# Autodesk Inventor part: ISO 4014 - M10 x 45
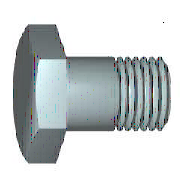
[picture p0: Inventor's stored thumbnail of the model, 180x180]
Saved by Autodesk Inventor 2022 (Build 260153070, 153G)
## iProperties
Created: 2021-02
Part Number: ISO 4014 - M10 x 45
Material: Acier inoxydable 440C
Description: Boulon à tête hexagonale - Produit de classes A et B
Document SubType Name: Modeling
Standard: ISO 4014
Designer: Fabian
Standard Revision: Fourth edition 2011-03-15
Standards Organization: ISO
Language: fr-FR
Size Designation: M10 x 45
Categories: <MemberInstance><Categories><Category DisplayName="Visserie" InternalName="e4da775c-781d-43d5-af7c-5136215cf5a6" Mnemonic="FSTN"><Category DisplayName="Vis" Int
Density: 7.75 g/cm^3
Appearance: Semi-poli
IsCustomPart: 0
Author: Fabian
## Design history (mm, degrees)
sketch "Esquisse1"
  geometry: L1 (0, 7.315)-(0, 5); L2 (19, 5)-(45, 5); L3 (45, 5)-(45, 0); L4 (45, 0)-(-0.6, 0); L5 (-9.72, 0)-(54.12, 0) reference; L6 (-0.6, 0)-(-0.6, 7.315); L7 (-0.6, 7.315)-(0, 7.315); L8 (19, 5)-(18.08, 5); L9 (18.08, 5)-(0, 5); L10 (0, -1.463)-(0, 8.778) reference
  constraints: 16 end point, 2 collinear, 2 perpendicular, 1 parallel
  dimensions: "d0" = 45 distance between parallel lines of L3 L1 (= NLG); "d1" = 26 distance from line of L2.start L3 (= GEL); "d2" = 10 diameter of L2 L4 (= GD); "d9" = 0.6001 distance between parallel lines of L6 L1 (computed from SD); "d10" = 14.63 diameter of L7 L4 (= SD2); "d13" = 0.92028 distance of L2.start L8.end (computed from GAL); "d14" = 10 diameter of L9 L4 (= BDM)
revolve "Corps" sketch "Esquisse1" stored, may be unused: angle "d12" = 90 deg
sketch "Esquisse2"
  geometry: L1 (0, 9.238)-(8, 4.619); L2 (8, 4.619)-(8, -4.619); L3 (8, -4.619)-(0, -9.238); L4 (0, -9.238)-(-8, -4.619); L5 (-8, -4.619)-(-8, 4.619); L6 (-8, 4.619)-(0, 9.238); 2 further points
  constraints: 12 end point, 1 coincident, 1 vertical, 11 other
  dimensions: "d11" = 16 distance between parallel lines of L5 L2 (= SW)
extrude "Tête" join sketch "Esquisse2" distance "d3" = 5.8 (= KOH - SD); taper "d4" = 0 deg
sketch "Esquisse4"
  geometry: L1 (-6.4, 8)-(-6.4, 9.238); L2 (-6.4, 9.238)-(-5.686, 9.238); L3 (-5.686, 9.238)-(-6.4, 8); L4 (-7.56, 0)-(0.56, 0) reference; L5 (-0.6, 9.238)-(-6.4, 9.238) reference; L6 (-6.4, 4.619)-(-6.4, 9.238) reference
  constraints: 6 end point, 2 collinear, 1 perpendicular, 1 vertical
  dimensions: "d5" = 30 deg angle of L3 L1 (= ANG1); "d19" = 16 diameter of L1.start L4 (= SW0)
revolve "Chanfrein1" sketch "Esquisse4" stored, may be unused: angle "d21" = 90 deg
workplane "Work Plane1"
body "Solid1"
feature "Filetage" dims "d15" = 26 (= GEL), "d16" = 0
chamfer "Chanfrein2" distance "d6" = 0.92018 (= -0.5 x SPD + 0.5 x GD); stored, may be unused: second distance "d7" = 0.92028 (computed from GUL), angle "d55" = 45 deg
other parameters: "NLG" = 45 [user parameter; used in 1 equation term], "GD" = 10 (= NND) [user parameter; used in 2 equation terms], "BDM" = 10 (= NND) [user parameter; used in 1 equation term], "KOH" = 6.4 [user parameter; used in 1 equation term], "GEL" = 26 [user parameter; used in 2 equation terms], "SW" = 16 [user parameter; used in 3 equation terms], "SW0" = 16 (= SW) [user parameter; used in 1 equation term], "SPD" = 8.15965 (= NND - 1.2269 x PTC) [user parameter; used in 1 equation term], "SD2" = 14.63 [user parameter; used in 2 equation terms], "SD" = 0.6 [user parameter; used in 2 equation terms], "ANG1" = 30 deg [user parameter; used in 1 equation term], "GAL" = 0.92018 (= 0.61345 x PTC) [user parameter; used in 1 equation term], "GUL" = 0.92018 (= 0.61345 x PTC) [user parameter; used in 1 equation term], "d8" = 0, "RR" = 0.4 [user parameter], "d57" = 0, "d58" = 0, "TPU" = 6.66667 (computed from PTC) [user parameter], "GD1" = 8.15965 (= THREADDIA - 1.2269 x PTC) [user parameter], "SDH" = 14.63 (= SD2) [user parameter], "TOA" = 30 deg [user parameter], "PTC" = 1.5 [user parameter; used in 5 equation terms], "E0" = 18.48 (= 1.155 x SW) [user parameter]
